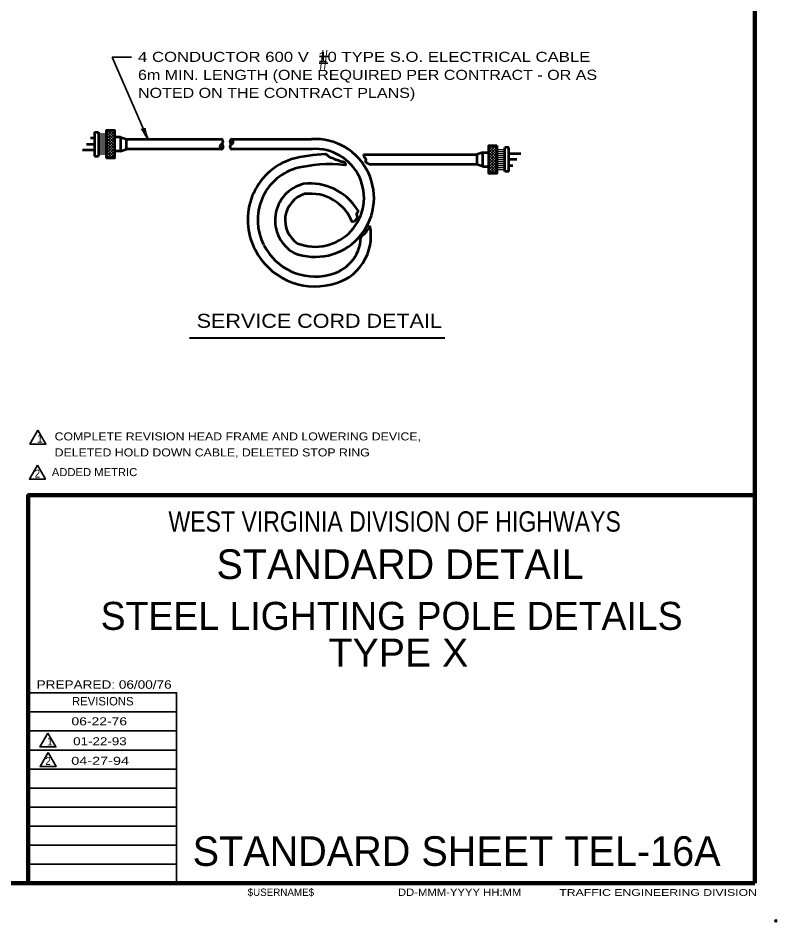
# Model space of a CAD drawing. Extents: x -24 to 689, y -7 to 446.
# Drawn here: x 499.2 to 688.9, y -7.4 to 218.4 of the extents above; entities that cross this region are included whole.
import ezdxf
from ezdxf.enums import TextEntityAlignment as Align

# ---------------------------------------------------------------- set-up
doc = ezdxf.new("R2010")
doc.units = 0
doc.header["$PDMODE"] = 32
doc.header["$PDSIZE"] = 0.5
doc.layers.add('1', color=7, linetype='Continuous', lineweight=35)
doc.layers.add('61', color=7, linetype='Continuous', lineweight=35)

msp = doc.modelspace()

# ---------------------------------------------------------------- linework, layer by layer
at = {"layer": '1', "lineweight": 158}
for q in [(683.413, 440.647), (683.413, 99.147), (23.747, 2.23)]:
    msp.add_line((683.413, 2.23), q, dxfattribs=at)
at = {"layer": '1', "lineweight": 13}
msp.add_line((683.413, 2.23), (683.413, 440.647), dxfattribs=at)
at = {"layer": '1'}
for p, q in [((531.609, 188.104), (522.704, 208.555)), ((527.561, 208.555), (522.704, 208.555)), ((538.83, 45.064), (501.747, 45.064)), ((538.83, 40.314), (501.747, 40.314)), ((538.83, 35.48), (501.747, 35.48)), ((538.83, 30.73), (501.747, 30.73)), ((538.83, 25.98), (501.747, 25.98)), ((538.83, 21.23), (501.747, 21.23)), ((538.83, 16.48), (501.747, 16.48)), ((538.83, 11.73), (501.747, 11.73)), ((538.83, 6.98), (501.747, 6.98))]:
    msp.add_line(p, q, dxfattribs=at)
at = {"layer": '1', "lineweight": 53}
for p, q in [((518.309, 189.854), (518.309, 183.854)), ((518.309, 189.854), (519.309, 189.854)), ((519.309, 189.854), (519.309, 183.854)), ((518.309, 188.354), (517.309, 188.354)), ((524.809, 188.604), (523.309, 188.604)), ((524.809, 188.604), (524.809, 185.104)), ((524.809, 188.604), (526.309, 188.104)), ((552.559, 188.104), (572.559, 188.104)), ((518.309, 185.354), (515.309, 185.354)), ((516.309, 186.854), (518.309, 186.854)), ((524.809, 185.104), (526.309, 185.604)), ((550.059, 185.604), (526.309, 185.604)), ((572.712, 185.604), (552.559, 185.604)), ((620.843, 180.003), (620.843, 186.003)), ((621.843, 186.003), (620.843, 186.003)), ((621.843, 180.003), (621.843, 186.003)), ((518.309, 183.854), (519.309, 183.854)), ((524.809, 185.104), (523.309, 185.104)), ((615.343, 184.753), (613.843, 184.253)), ((615.343, 181.253), (615.343, 184.753)), ((615.343, 184.753), (616.843, 184.753)), ((621.843, 184.503), (624.843, 184.503)), ((623.843, 183.003), (621.843, 183.003)), ((615.343, 181.253), (613.843, 181.753)), ((615.343, 181.253), (616.843, 181.253)), ((621.843, 181.503), (622.843, 181.503)), ((621.843, 180.003), (620.843, 180.003))]:
    msp.add_line(p, q, dxfattribs=at)
at = {"layer": '1', "lineweight": 25}
for p, q in [((521.309, 190.182), (521.481, 190.354)), ((521.309, 189.475), (522.188, 190.354)), ((521.309, 188.767), (522.895, 190.354)), ((521.309, 188.06), (523.309, 190.06)), ((523.309, 187.874), (521.309, 189.874)), ((523.309, 188.581), (521.535, 190.354)), ((523.309, 189.288), (522.242, 190.354)), ((523.309, 189.995), (522.95, 190.354)), ((521.309, 189.354), (519.309, 189.354)), ((521.309, 188.854), (519.309, 188.854)), ((521.309, 188.354), (519.309, 188.354)), ((521.309, 187.854), (519.309, 187.854)), ((521.309, 187.353), (523.309, 189.353)), ((523.309, 187.167), (521.309, 189.167)), ((521.309, 186.646), (523.309, 188.646)), ((523.309, 186.46), (521.309, 188.46)), ((521.309, 185.939), (523.309, 187.939)), ((523.309, 185.753), (521.309, 187.753)), ((521.309, 187.354), (519.309, 187.354)), ((521.309, 186.854), (519.309, 186.854)), ((521.309, 186.354), (519.309, 186.354)), ((521.309, 185.854), (519.309, 185.854)), ((521.309, 185.354), (519.309, 185.354)), ((521.309, 185.232), (523.309, 187.232)), ((523.309, 185.046), (521.309, 187.046)), ((521.309, 184.525), (523.309, 186.525)), ((523.309, 184.338), (521.309, 186.338)), ((521.309, 183.818), (523.309, 185.818)), ((523.309, 183.631), (521.309, 185.631)), ((618.599, 186.503), (616.843, 184.747)), ((617.892, 186.503), (616.843, 185.454)), ((617.185, 186.503), (616.843, 186.161)), ((616.843, 186.226), (618.843, 184.226)), ((618.843, 186.04), (616.843, 184.04)), ((616.843, 185.519), (618.843, 183.519)), ((618.843, 185.332), (616.843, 183.332)), ((617.273, 186.503), (618.843, 184.933)), ((617.98, 186.503), (618.843, 185.64)), ((618.687, 186.503), (618.843, 186.347)), ((618.843, 185.503), (620.843, 185.503)), ((521.309, 184.854), (519.309, 184.854)), ((521.309, 184.354), (519.309, 184.354)), ((522.879, 183.354), (521.309, 184.924)), ((522.171, 183.354), (521.309, 184.217)), ((521.464, 183.354), (521.309, 183.51)), ((521.552, 183.354), (523.309, 185.111)), ((522.259, 183.354), (523.309, 184.404)), ((522.967, 183.354), (523.309, 183.696)), ((616.843, 184.812), (618.843, 182.812)), ((618.843, 184.625), (616.843, 182.625)), ((616.843, 184.105), (618.843, 182.105)), ((618.843, 183.918), (616.843, 181.918)), ((616.843, 183.398), (618.843, 181.398)), ((618.843, 183.211), (616.843, 181.211)), ((618.843, 185.003), (620.843, 185.003)), ((618.843, 184.503), (620.843, 184.503)), ((618.843, 184.003), (620.843, 184.003)), ((618.843, 183.503), (620.843, 183.503)), ((618.843, 183.003), (620.843, 183.003)), ((616.843, 182.69), (618.843, 180.69)), ((618.843, 182.504), (616.843, 180.504)), ((616.843, 181.983), (618.843, 179.983)), ((618.843, 181.797), (616.843, 179.797)), ((616.843, 181.276), (618.616, 179.503)), ((618.843, 181.09), (617.256, 179.503)), ((618.843, 182.503), (620.843, 182.503)), ((618.843, 182.003), (620.843, 182.003)), ((618.843, 181.503), (620.843, 181.503)), ((618.843, 181.003), (620.843, 181.003)), ((616.843, 180.569), (617.909, 179.503)), ((616.843, 179.862), (617.202, 179.503)), ((618.843, 180.383), (617.963, 179.503)), ((618.843, 179.676), (618.67, 179.503)), ((618.843, 180.503), (620.843, 180.503))]:
    msp.add_line(p, q, dxfattribs=at)
at = {"layer": '1', "lineweight": 40}
msp.add_line((542.028, 138.49), (605.888, 138.49), dxfattribs=at)
at = {"layer": '1', "lineweight": 53}
for points in [[(521.309, 183.354), (521.309, 190.354), (523.309, 190.354), (523.309, 183.354)], [(618.843, 186.503), (618.843, 179.503), (616.843, 179.503), (616.843, 186.503)]]:
    msp.add_lwpolyline(points, close=True, dxfattribs=at)
for points in [[(526.309, 185.604), (526.309, 188.104), (550.059, 188.104)], [(585.566, 184.253), (613.843, 184.253), (613.843, 181.753), (587.365, 181.753)]]:
    msp.add_lwpolyline(points, dxfattribs=at)
at = {"layer": '1'}
for points in [[(504.149, 115.4), (502.149, 111.936), (506.149, 111.936)], [(504.007, 106.642), (502.007, 103.178), (506.007, 103.178)], [(506.644, 39.738), (504.644, 36.274), (508.644, 36.274)], [(506.691, 34.854), (504.691, 31.39), (508.691, 31.39)]]:
    msp.add_lwpolyline(points, close=True, dxfattribs=at)
at = {"layer": '1', "lineweight": 158}
msp.add_lwpolyline([(501.747, 2.23), (501.747, 99.147), (683.413, 99.147)], dxfattribs=at)
at = {"layer": '1'}
msp.add_lwpolyline([(538.83, 2.23), (538.83, 49.814), (501.747, 49.814)], dxfattribs=at)
at = {"layer": '1', "lineweight": 53}
for centre, radius, start, end in [((549.73, 187.479), 0.706, 297.75189, 62.24811), ((552.86, 187.479), 0.694, 115.76424, 244.23576), ((552.286, 187.479), 0.694, 295.76424, 64.23576), ((573.46, 173.42), 14.712, 248.92664, 93.51269), ((550.333, 186.229), 0.665, 110.01746, 249.98254), ((549.823, 186.229), 0.668, 290.62029, 69.37971), ((552.86, 186.229), 0.694, 115.76424, 244.23576), ((573.469, 173.459), 12.212, 248.92664, 93.51269), ((572.53, 167.95), 15.941, 108.16556, 207.79267), ((577.127, 147.163), 37.193, 91.64258, 104.90932), ((572.53, 167.95), 13.441, 108.16556, 207.20957), ((577.127, 147.163), 34.693, 83.67368, 104.54428), ((572.804, 167.834), 9.369, 104.10799, 240.35478), ((572.227, 163.185), 13.842, 31.61739, 97.08099), ((572.804, 167.834), 6.869, 106.73846, 237.14925), ((572.224, 163.158), 11.342, 21.22901, 97.08099), ((575.054, 163.927), 12.358, 281.24918, 11.93102), ((575.054, 163.927), 9.858, 281.24918, 357.69166), ((573.407, 168.073), 16.77, 206.76656, 284.17816), ((573.407, 168.073), 14.27, 206.76656, 284.17816)]:
    msp.add_arc(centre, radius, start, end, dxfattribs=at)
at = {"layer": '1', "lineweight": 40}
for centre, major_axis, ratio, start_param, end_param in [((530.92, 188.994), (0.856, -1.575), 0.122415, 0.8963533, 3.1415927), ((531.355, 189.216), (0.54, -1.681), 0.07063, 3.1407148, 5.41811)]:
    msp.add_ellipse(centre, major_axis=major_axis, ratio=ratio, start_param=start_param, end_param=end_param, dxfattribs=at)
at = {"layer": '1', "lineweight": 53}
for points in [[(580.95, 181.644), (581.096, 181.69), (580.784, 182.27), (580.026, 182.47), (579.29, 182.805), (578.421, 183.006), (577.975, 183.296), (577.061, 183.585), (576.726, 183.942), (576.061, 184.34)], [(587.365, 181.753), (586.781, 181.913), (586.38, 182.18), (586.068, 182.515), (586.246, 182.961), (585.956, 183.362), (585.8, 183.608), (585.566, 184.253)], [(584.014, 170.441), (584.1, 169.927), (583.908, 169.602), (583.804, 169.262), (583.967, 168.804), (583.848, 168.316), (583.331, 167.607), (582.796, 167.264)], [(587.145, 166.482), (586.907, 166.025), (586.759, 165.612), (586.36, 165.272), (586.094, 164.828), (585.651, 164.34), (585.415, 164.163), (585.03, 163.838), (584.904, 163.53)]]:
    msp.add_spline(points, degree=3, dxfattribs=at)
at = {"layer": '1'}
msp.add_point((688.663, -7.186), dxfattribs=at)
at = {"layer": '61', "lineweight": 53}
for q in [(556.163, 2.23), (556.163, 2.23), (556.163, 2.23), (556.413, 2.23), (556.413, 2.23)]:
    msp.add_line((683.413, 2.23), q, dxfattribs=at)

# ---------------------------------------------------------------- texts
at = {"layer": '1'}
for s, height, width, p in [('#', 5, 0.65, (575.605, 205.45)), ('SERVICE CORD DETAIL', 3.5, 1.15, (574.494, 140.976)), ('2', 2, 0.9, (504.007, 103.553)), ('WEST VIRGINIA DIVISION OF HIGHWAYS', 5.074, 0.85, (593.33, 90.064)), ('TYPE X', 6.993, 1.05, (594.276, 56.348)), ('06-22-76', 2, 1.3, (519.48, 41.681)), ('01-22-93', 2, 1.25, (519.647, 36.7)), ('2', 2, 0.9, (506.691, 31.765)), ('04-27-94', 2, 1.35, (519.701, 31.815))]:
    msp.add_text(s, height=height, dxfattribs=dict(at, width=width)).set_placement(p, align=Align.CENTER)
for s, height, width, p in [('4 CONDUCTOR 600 V  10 TYPE S.O. ELECTRICAL CABLE', 2.5, 1.25, (529.17, 207.424)), ('6m MIN. LENGTH (ONE REQUIRED PER CONTRACT - OR AS', 2.5, 1.2, (529.17, 202.924)), ('NOTED ON THE CONTRACT PLANS)', 2.5, 1.2, (529.17, 198.424)), ('COMPLETE REVISION HEAD FRAME AND LOWERING DEVICE,', 2, 1.15, (508.326, 112.851)), ('DELETED HOLD DOWN CABLE, DELETED STOP RING', 2, 1.15, (508.326, 108.851)), ('ADDED METRIC', 2, 1.05, (507.616, 103.932)), ('PREPARED: 06/00/76', 2.114, 1.2, (503.83, 50.814)), ('DD-MMM-YYYY HH:MM', 1.833, 1.15, (594.163, -0.936)), ('TRAFFIC ENGINEERING DIVISION', 1.693, 1.35, (634.497, -0.936))]:
    msp.add_text(s, height=height, dxfattribs=dict(at, width=width)).set_placement(p)
for s, height, p in [('1', 2, (504.663, 112.311)), ('STANDARD DETAIL', 7.401, (594.705, 78.23)), ('STEEL LIGHTING POLE DETAILS', 6.993, (592.577, 65.525)), ('1', 2, (507.158, 36.649))]:
    msp.add_text(s, height=height, dxfattribs=at).set_placement(p, align=Align.CENTER)
for s, height, p in [('REVISIONS', 2.114, (512.663, 46.647)), ('STANDARD SHEET TEL-16A', 7.401, (542.83, 6.564)), ('$USERNAME$', 1.833, (556.58, -0.936))]:
    msp.add_text(s, height=height, dxfattribs=at).set_placement(p)

doc.saveas('drawing.dxf')
